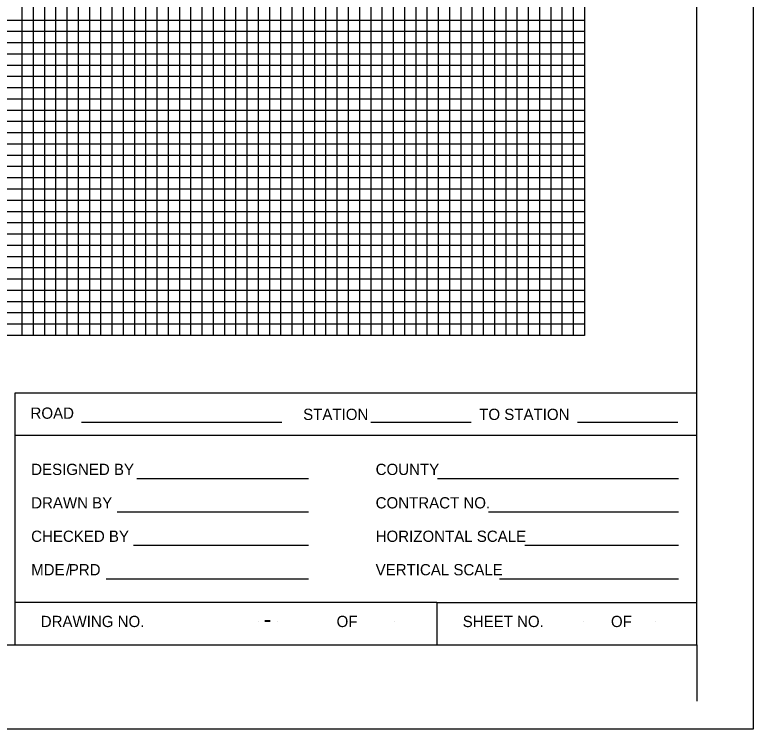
# Model space of a CAD drawing. Extents: x 0 to 34, y 0 to 25.5.
# Drawn here: x 27.44 to 34, y 0 to 6.35 of the extents above; entities that cross this region are included whole.
import ezdxf

# ---------------------------------------------------------------- set-up
doc = ezdxf.new("R2010")
doc.units = 0
for name, color, linetype in [('BORD-LINE', 7, 'Continuous'), ('TTLB-PROF', 7, 'Continuous'), ('TTLB-TEXT', 7, 'Continuous'), ('USER-LINE', 7, 'Continuous'), ('USER-PAGE', 7, 'Continuous'), ('XSEC-MAJR', 7, 'Continuous'), ('XSEC-MINR', 7, 'Continuous')]:
    doc.layers.add(name, color=color, linetype=linetype)

msp = doc.modelspace()

# ---------------------------------------------------------------- linework, layer by layer
at = {"layer": 'BORD-LINE'}
for p, q in [((33.4999, 0.75), (33.4999, 21.5)), ((33.4998, 2.9861), (27.4368, 2.9861)), ((27.4369, 2.9861), (27.4369, 0.75)), ((33.4998, 2.6111), (27.4368, 2.6111)), ((31.1869, 1.125), (27.4369, 1.125)), ((31.1869, 1.125), (31.1869, 0.75)), ((31.1869, 1.125), (33.4999, 1.125)), ((1.5, 0.75), (33.4999, 0.75)), ((33.4999, 0.75), (33.4999, 0.25))]:
    msp.add_line(p, q, dxfattribs=at)
at = {"layer": 'TTLB-PROF'}
for p, q in [((31.9693, 1.6352), (33.3364, 1.6352)), ((31.7439, 1.338), (33.3364, 1.338))]:
    msp.add_line(p, q, dxfattribs=at)
at = {"layer": 'TTLB-TEXT'}
for p, q in [((28.0285, 2.7295), (29.8116, 2.7295)), ((30.6, 2.7295), (31.4933, 2.7295)), ((32.4372, 2.7295), (33.3305, 2.7295)), ((28.5219, 2.2296), (30.0474, 2.2296)), ((31.1939, 2.2296), (33.3364, 2.2296)), ((28.3484, 1.9324), (30.0474, 1.9324)), ((31.6459, 1.9324), (33.3364, 1.9324)), ((28.4919, 1.6352), (30.0474, 1.6352)), ((28.2493, 1.338), (30.0474, 1.338)), ((29.6057, 0.9579), (29.6057, 0.9579)), ((29.7748, 0.9579), (29.7748, 0.9579)), ((30.8151, 0.9579), (30.8151, 0.9579)), ((32.4955, 0.9579), (32.4955, 0.9579)), ((33.1281, 0.9579), (33.1281, 0.9579))]:
    msp.add_line(p, q, dxfattribs=at)
at = {"layer": 'USER-LINE'}
msp.add_line((33.9999, 0), (33.9999, 0), dxfattribs=at)
at = {"layer": 'USER-PAGE'}
msp.add_lwpolyline([(0, 22), (34, 22), (34, 0), (0, 0)], close=True, dxfattribs=at)
at = {"layer": 'XSEC-MAJR'}
for p, q in [((27.5, 20.5), (27.5, 3.5)), ((28.5, 20.5), (28.5, 3.5)), ((29.5, 20.5), (29.5, 3.5)), ((30.5, 20.5), (30.5, 3.5)), ((31.5, 20.5), (31.5, 3.5)), ((32.5, 20.5), (32.5, 3.5)), ((32.5, 5.5), (2.5, 5.5)), ((32.5, 4.5), (2.5, 4.5)), ((32.5, 3.5), (2.5, 3.5))]:
    msp.add_line(p, q, dxfattribs=at)
at = {"layer": 'XSEC-MINR'}
for p, q in [((27.6, 20.5), (27.6, 3.5)), ((27.7, 20.5), (27.7, 3.5)), ((27.8, 20.5), (27.8, 3.5)), ((27.9, 20.5), (27.9, 3.5)), ((28, 20.5), (28, 3.5)), ((28.1, 20.5), (28.1, 3.5)), ((28.2, 20.5), (28.2, 3.5)), ((28.3, 20.5), (28.3, 3.5)), ((28.4, 20.5), (28.4, 3.5)), ((28.6, 20.5), (28.6, 3.5)), ((28.7, 20.5), (28.7, 3.5)), ((28.8, 20.5), (28.8, 3.5)), ((28.9, 20.5), (28.9, 3.5)), ((29, 20.5), (29, 3.5)), ((29.1, 20.5), (29.1, 3.5)), ((29.2, 20.5), (29.2, 3.5)), ((29.3, 20.5), (29.3, 3.5)), ((29.4, 20.5), (29.4, 3.5)), ((29.6, 20.5), (29.6, 3.5)), ((29.7, 20.5), (29.7, 3.5)), ((29.8, 20.5), (29.8, 3.5)), ((29.9, 20.5), (29.9, 3.5)), ((30, 20.5), (30, 3.5)), ((30.1, 20.5), (30.1, 3.5)), ((30.2, 20.5), (30.2, 3.5)), ((30.3, 20.5), (30.3, 3.5)), ((30.4, 20.5), (30.4, 3.5)), ((30.6, 20.5), (30.6, 3.5)), ((30.7, 20.5), (30.7, 3.5)), ((30.8, 20.5), (30.8, 3.5)), ((30.9, 20.5), (30.9, 3.5)), ((31, 20.5), (31, 3.5)), ((31.1, 20.5), (31.1, 3.5)), ((31.2, 20.5), (31.2, 3.5)), ((31.3, 20.5), (31.3, 3.5)), ((31.4, 20.5), (31.4, 3.5)), ((31.6, 20.5), (31.6, 3.5)), ((31.7, 20.5), (31.7, 3.5)), ((31.8, 20.5), (31.8, 3.5)), ((31.9, 20.5), (31.9, 3.5)), ((32, 20.5), (32, 3.5)), ((32.1, 20.5), (32.1, 3.5)), ((32.2, 20.5), (32.2, 3.5)), ((32.3, 20.5), (32.3, 3.5)), ((32.4, 20.5), (32.4, 3.5)), ((32.5, 6.3), (2.5, 6.3)), ((32.5, 6.2), (2.5, 6.2)), ((32.5, 6.1), (2.5, 6.1)), ((32.5, 6), (2.5, 6)), ((32.5, 5.9), (2.5, 5.9)), ((32.5, 5.8), (2.5, 5.8)), ((32.5, 5.7), (2.5, 5.7)), ((32.5, 5.6), (2.5, 5.6)), ((32.5, 5.4), (2.5, 5.4)), ((32.5, 5.3), (2.5, 5.3)), ((32.5, 5.2), (2.5, 5.2)), ((32.5, 5.1), (2.5, 5.1)), ((32.5, 5), (2.5, 5)), ((32.5, 4.9), (2.5, 4.9)), ((32.5, 4.8), (2.5, 4.8)), ((32.5, 4.7), (2.5, 4.7)), ((32.5, 4.6), (2.5, 4.6)), ((32.5, 4.4), (2.5, 4.4)), ((32.5, 4.3), (2.5, 4.3)), ((32.5, 4.2), (2.5, 4.2)), ((32.5, 4.1), (2.5, 4.1)), ((32.5, 4), (2.5, 4)), ((32.5, 3.9), (2.5, 3.9)), ((32.5, 3.8), (2.5, 3.8)), ((32.5, 3.7), (2.5, 3.7)), ((32.5, 3.6), (2.5, 3.6))]:
    msp.add_line(p, q, dxfattribs=at)

# ---------------------------------------------------------------- texts
at = {"layer": 'TTLB-PROF'}
for s, p in [('HORIZONTAL SCALE', (30.6442, 1.6651)), ('VERTICAL SCALE', (30.6442, 1.3679))]:
    msp.add_text(s, height=0.1, dxfattribs=at).set_placement(p)
at = {"layer": 'TTLB-TEXT'}
for s, height, p in [('ROAD', 0.1, (27.5768, 2.7594)), ('STATION', 0.1, (29.9999, 2.7486)), ('TO STATION', 0.1, (31.5645, 2.7486)), ('DESIGNED BY', 0.1, (27.5827, 2.2595)), ('COUNTY', 0.1, (30.6442, 2.2595)), ('DRAWN BY', 0.1, (27.5827, 1.9623)), ('CHECKED BY', 0.1, (27.5827, 1.6651)), ('MDE PRD', 0.1, (27.5827, 1.3679)), ('/', 0.1, (27.8908, 1.3653)), ('DRAWING NO.', 0.1, (27.6679, 0.9079)), ('OF', 0.1, (30.297, 0.9079)), ('SHEET NO.', 0.1, (31.4179, 0.9079)), ('OF', 0.1, (32.7356, 0.9079)), ('-', 0.16, (29.6475, 0.9013))]:
    msp.add_text(s, height=height, dxfattribs=at).set_placement(p)
msp.add_text('CONTRACT NO.', height=0.1, rotation=359.99999, dxfattribs=at).set_placement((30.6442, 1.9623))

doc.saveas('drawing.dxf')
